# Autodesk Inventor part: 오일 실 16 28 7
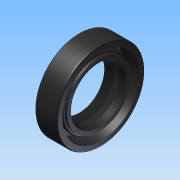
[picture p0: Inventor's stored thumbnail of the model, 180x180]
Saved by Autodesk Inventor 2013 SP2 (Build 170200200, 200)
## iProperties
Created: 2026-10
Part Number: 오일 실 16 28 7
Material: Generic
Document SubType Name: Modeling
Designer: a
Density: 1 g/cm^3
Author: a
변환 표준: STEP AP214IS
전처리기: Build: 200, Release: 2013 SP2 Update 6 - Date: Thu 07/17/2014
전송 단위: 밀리미터
불확실성: 0.01
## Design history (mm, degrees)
node "오일 실 16 28 71"
body "Solid1"
node "기준1"
